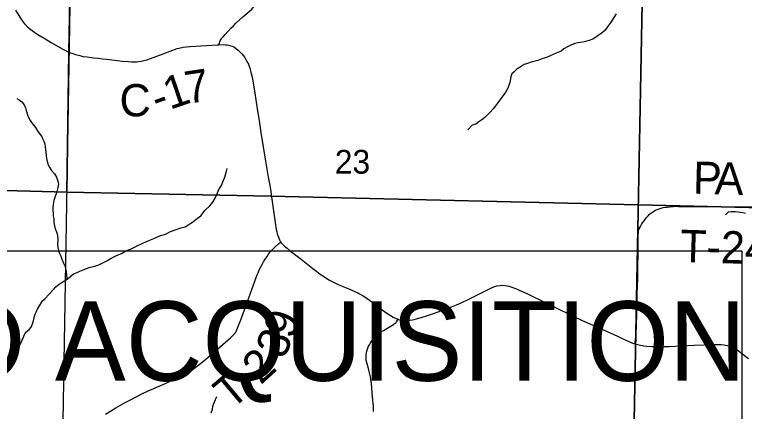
# Model space of a CAD drawing. Extents: x 0 to 34, y 0 to 22.
# Drawn here: x 11.356 to 12.641, y 17.147 to 17.845 of the extents above; entities that cross this region are included whole.
import ezdxf

# ---------------------------------------------------------------- set-up
doc = ezdxf.new("R2010")
doc.units = 0
for name, color, linetype in [('GM_X_Corporation', 7, 'Continuous'), ('GM_X_County_Road', 7, 'Continuous'), ('GM_X_County_Road_Text', 7, 'Continuous'), ('GM_X_Minor_River', 7, 'Continuous'), ('GM_X_Section_Text', 7, 'Continuous'), ('GM_X_Township_Road', 7, 'Continuous'), ('GM_X_Township_Road_Text', 7, 'Continuous'), ('SH_Text', 7, 'Continuous')]:
    doc.layers.add(name, color=color, linetype=linetype)

msp = doc.modelspace()

# ---------------------------------------------------------------- linework, layer by layer
at = {"layer": 'GM_X_Corporation'}
for points in [[(11.5001, 20.4), (10.6, 20.4), (10.6, 17.5523), (10.9447, 17.5459), (11.0329, 17.5442), (11.4477, 17.5329), (11.4514, 17.7789), (11.4741, 19.003), (11.486, 19.6423), (11.498, 20.2911)], [(10.6, 18.0532), (10.6, 17.0429), (11.4395, 17.0255), (11.4565, 18.0343)], [(11.4565, 18.0343), (12.4638, 18.0185), (12.4446, 17.0089), (11.4395, 17.0255)], [(12.4638, 18.0185), (13.4723, 18.0001), (13.4493, 16.9912), (12.4446, 17.0089)]]:
    msp.add_lwpolyline(points, close=True, dxfattribs=at)
for points in [[(16.7661, 20.4), (11.5001, 20.4), (11.498, 20.2911), (11.486, 19.6423), (11.4741, 19.003), (11.4514, 17.7789), (11.4477, 17.5329), (11.8073, 17.526), (12.504, 17.5091), (12.7693, 17.5027), (12.7967, 17.502), (13.2742, 17.4966), (14.0954, 17.4811)], [(14.0954, 17.4811), (13.2742, 17.4966), (12.7967, 17.502), (12.7693, 17.5027), (12.504, 17.5091), (11.8073, 17.526), (11.4477, 17.5329), (11.0329, 17.5442), (10.9447, 17.5459), (10.9437, 17.4908), (10.9418, 17.3896), (10.9206, 16.4568), (10.9139, 16.0819), (10.9086, 15.7107), (10.9052, 15.3502), (10.897, 14.5214)]]:
    msp.add_lwpolyline(points, dxfattribs=at)
at = {"layer": 'GM_X_County_Road'}
for points in [[(11.3577, 17.8529), (11.368, 17.8358), (11.3697, 17.8337), (11.3732, 17.8292), (11.3753, 17.827), (11.3794, 17.8232), (11.3842, 17.8192), (11.3914, 17.8139), (11.3967, 17.8103), (11.4079, 17.8037), (11.4205, 17.7963), (11.4354, 17.7875), (11.4405, 17.7846), (11.4489, 17.7804), (11.454, 17.7781), (11.4564, 17.7772)], [(11.4564, 17.7772), (11.4633, 17.775), (11.4707, 17.7731), (11.4763, 17.7718), (11.4836, 17.7707), (11.4948, 17.7693), (11.5031, 17.7684), (11.5107, 17.7676), (11.5175, 17.7667), (11.5271, 17.7657), (11.5369, 17.7646), (11.5453, 17.7635), (11.5567, 17.7625), (11.5616, 17.7622), (11.5672, 17.7621), (11.5709, 17.7622), (11.5745, 17.7626), (11.579, 17.7632), (11.5835, 17.7643), (11.5885, 17.7659), (11.5949, 17.768), (11.6173, 17.7761), (11.6423, 17.7854), (11.6478, 17.7869), (11.653, 17.7879), (11.6586, 17.7888), (11.6642, 17.7892), (11.6757, 17.7899), (11.6837, 17.7904), (11.6937, 17.7911), (11.7128, 17.7921), (11.7157, 17.7923), (11.7231, 17.7926), (11.727, 17.7923), (11.7296, 17.792), (11.7332, 17.7914), (11.7362, 17.7906), (11.7391, 17.7896), (11.7417, 17.7883), (11.7444, 17.7867), (11.7472, 17.7845), (11.7498, 17.7824), (11.753, 17.7793), (11.7559, 17.7763), (11.7586, 17.7731), (11.7613, 17.7695), (11.7633, 17.7664), (11.7651, 17.7629), (11.7676, 17.7578), (11.77, 17.751), (11.772, 17.7442), (11.7742, 17.7351), (11.7772, 17.7184), (11.779, 17.7069), (11.7831, 17.6793), (11.7859, 17.6624), (11.7897, 17.6378), (11.7979, 17.5872), (11.8026, 17.5591), (11.8051, 17.5444), (11.8063, 17.5374), (11.8089, 17.5208)], [(11.8089, 17.5208), (11.8168, 17.4671), (11.8176, 17.4632), (11.8184, 17.4597), (11.8193, 17.4566), (11.8216, 17.4508), (11.8226, 17.4488), (11.8237, 17.4468), (11.8247, 17.4452), (11.8256, 17.4439), (11.8272, 17.4419), (11.829, 17.44), (11.8312, 17.4379), (11.8356, 17.4341), (11.8419, 17.429), (11.8603, 17.4148), (11.8813, 17.3985), (11.888, 17.3933), (11.8942, 17.3887), (11.9034, 17.3825), (11.9094, 17.3788), (11.9129, 17.3767), (11.9219, 17.3721), (11.9256, 17.3703), (11.9346, 17.3666), (11.9398, 17.3646), (11.9461, 17.362), (11.9512, 17.3598), (11.9603, 17.3557), (11.9634, 17.3541), (11.97, 17.3504), (11.9729, 17.3486), (11.9809, 17.343), (11.987, 17.3387), (11.9951, 17.3325), (12.0033, 17.3257), (12.0113, 17.32), (12.0161, 17.3169), (12.0225, 17.313), (12.025, 17.3116), (12.0295, 17.3097), (12.0311, 17.3092), (12.0321, 17.3088), (12.0376, 17.3076), (12.04, 17.3072), (12.0423, 17.307), (12.0482, 17.3072), (12.0521, 17.3075), (12.0567, 17.3083), (12.0612, 17.3093), (12.0677, 17.3111), (12.0796, 17.3147), (12.0885, 17.3176), (12.1019, 17.3224), (12.1255, 17.3312), (12.1339, 17.3345), (12.1413, 17.3378), (12.158, 17.3458), (12.1664, 17.3501), (12.1908, 17.3624), (12.1969, 17.3652), (12.2019, 17.3668), (12.2053, 17.3678), (12.2109, 17.3687), (12.2131, 17.3689), (12.22, 17.3687), (12.2233, 17.3682), (12.2264, 17.3675), (12.2298, 17.3664), (12.2395, 17.3627), (12.2447, 17.3605), (12.2579, 17.3543), (12.2688, 17.3492), (12.3017, 17.3335), (12.3146, 17.3272), (12.3289, 17.3202), (12.3422, 17.3137), (12.3543, 17.3079), (12.3648, 17.3032), (12.41, 17.2829), (12.419, 17.2786), (12.4337, 17.2716), (12.4378, 17.2698), (12.4443, 17.2673), (12.4463, 17.2666), (12.448, 17.2661), (12.4533, 17.2648), (12.458, 17.2637), (12.4639, 17.2625), (12.4695, 17.262), (12.4779, 17.2614), (12.493, 17.2611), (12.5084, 17.2614), (12.5521, 17.2637), (12.5891, 17.265), (12.6005, 17.2647), (12.6058, 17.2641), (12.6079, 17.2637), (12.6113, 17.2629), (12.6149, 17.2618), (12.6175, 17.2608), (12.6241, 17.2579), (12.6267, 17.2564), (12.6302, 17.2541), (12.6339, 17.2515), (12.6486, 17.2402)]]:
    msp.add_lwpolyline(points, dxfattribs=at)
at = {"layer": 'GM_X_Minor_River'}
for points in [[(12.4155, 17.8467), (12.408, 17.8353), (12.405, 17.8304), (12.4012, 17.8254), (12.3959, 17.8178), (12.391, 17.8136), (12.3853, 17.8098), (12.3789, 17.8049), (12.3743, 17.8018), (12.3679, 17.7995), (12.3588, 17.7972), (12.3527, 17.7961), (12.3478, 17.7957), (12.3424, 17.7946), (12.3352, 17.7915), (12.3296, 17.7888), (12.3231, 17.785), (12.3182, 17.7812), (12.3099, 17.7774), (12.2992, 17.7729), (12.2924, 17.7698), (12.2864, 17.7679), (12.2773, 17.7645), (12.2727, 17.7633), (12.2655, 17.7618), (12.259, 17.7591)], [(12.259, 17.7591), (12.2534, 17.7572), (12.2462, 17.753), (12.2405, 17.7492), (12.2359, 17.7447), (12.2314, 17.7412), (12.2299, 17.7359), (12.228, 17.726), (12.2262, 17.7207), (12.2243, 17.7158), (12.2197, 17.7074), (12.2137, 17.7002), (12.2111, 17.6956), (12.2065, 17.6896), (12.2031, 17.6846), (12.1986, 17.6797), (12.1933, 17.6736), (12.1887, 17.669), (12.1842, 17.6641), (12.1789, 17.6603), (12.1736, 17.6568), (12.1679, 17.6527), (12.1615, 17.6508), (12.1539, 17.6428)], [(11.3595, 17.6977), (11.3641, 17.6954), (11.3686, 17.692), (11.3728, 17.6867), (11.3751, 17.681), (11.3763, 17.6764), (11.3786, 17.6688), (11.3805, 17.6643), (11.3832, 17.659), (11.3874, 17.6533), (11.3927, 17.6464), (11.3969, 17.6396), (11.403, 17.6316), (11.4049, 17.6271), (11.4072, 17.6225), (11.4091, 17.6176), (11.4099, 17.6123), (11.4111, 17.6035), (11.4115, 17.5975), (11.4119, 17.5918), (11.4142, 17.5819), (11.418, 17.5758), (11.4211, 17.5709), (11.426, 17.5648), (11.4295, 17.5591), (11.4321, 17.5519), (11.4329, 17.547), (11.4322, 17.5409), (11.4296, 17.5318), (11.4273, 17.5253), (11.4247, 17.5181), (11.4236, 17.5109), (11.4232, 17.506), (11.4232, 17.5006), (11.4236, 17.4953), (11.424, 17.4904), (11.4248, 17.4858), (11.4252, 17.4794), (11.4263, 17.4737), (11.4275, 17.4684), (11.4294, 17.4631), (11.4313, 17.4574), (11.4318, 17.4483), (11.4314, 17.4418), (11.4318, 17.4353), (11.433, 17.43), (11.4349, 17.4251), (11.4372, 17.4202), (11.4391, 17.4148), (11.4421, 17.408), (11.4444, 17.4031), (11.4456, 17.3985), (11.4467, 17.3928), (11.4475, 17.3879), (11.4481, 17.38)], [(11.6613, 17.4755), (11.6689, 17.48), (11.678, 17.4869), (11.6837, 17.491), (11.6871, 17.4956), (11.6912, 17.5013), (11.6999, 17.5089), (11.7052, 17.515), (11.709, 17.5222), (11.712, 17.529), (11.7154, 17.5378), (11.7207, 17.5458), (11.7226, 17.5511), (11.726, 17.5591), (11.7297, 17.572), (11.7305, 17.5745)], [(12.6434, 17.4951), (12.6385, 17.4962), (12.6301, 17.4977), (12.6248, 17.4981), (12.6187, 17.4981), (12.6127, 17.4977), (12.6081, 17.4931)], [(11.3554, 17.2507), (11.3595, 17.256), (11.3652, 17.2636), (11.3682, 17.2693), (11.372, 17.2792), (11.375, 17.2857), (11.3814, 17.291), (11.3848, 17.2955), (11.3875, 17.3009), (11.389, 17.3066), (11.3901, 17.3115), (11.3916, 17.3168), (11.3938, 17.3218), (11.3961, 17.3271), (11.3999, 17.3328), (11.4048, 17.3415), (11.4097, 17.3457), (11.4161, 17.3525), (11.4245, 17.3617), (11.4282, 17.3662), (11.4343, 17.3712), (11.4396, 17.3746), (11.4464, 17.3788), (11.4547, 17.3852), (11.4597, 17.389), (11.4661, 17.3917), (11.471, 17.3936), (11.4767, 17.3959), (11.487, 17.4001), (11.4991, 17.4031), (11.504, 17.405), (11.5184, 17.4123), (11.5271, 17.4172), (11.5332, 17.4203), (11.5393, 17.4229), (11.5442, 17.4252), (11.5518, 17.4298), (11.5601, 17.4324), (11.5719, 17.4385), (11.5817, 17.4431), (11.5923, 17.448), (11.6011, 17.4515), (11.6128, 17.4564), (11.6196, 17.4583), (11.6242, 17.4602), (11.6306, 17.4636), (11.6424, 17.4678), (11.6484, 17.4701), (11.6564, 17.4717), (11.6613, 17.4755)], [(11.7023, 17.1448), (11.7042, 17.1512), (11.705, 17.1558), (11.7068, 17.1607), (11.7095, 17.1679), (11.7123, 17.1733)]]:
    msp.add_lwpolyline(points, dxfattribs=at)
at = {"layer": 'GM_X_Township_Road'}
for points in [[(11.7157, 17.7923), (11.7167, 17.7956), (11.718, 17.7993), (11.7194, 17.8018), (11.7206, 17.8036), (11.7229, 17.8063), (11.7265, 17.8105), (11.7369, 17.8213), (11.7413, 17.8257), (11.7457, 17.8302), (11.7515, 17.8355), (11.7577, 17.8411), (11.765, 17.8474), (11.7735, 17.8551), (11.7756, 17.857), (11.7782, 17.8601), (11.7816, 17.8646)], [(12.448, 17.2661), (12.4485, 17.2679), (12.4496, 17.2745), (12.4498, 17.277), (12.4507, 17.2889), (12.4509, 17.2944), (12.4525, 17.3542), (12.4529, 17.3682), (12.4532, 17.3801), (12.4537, 17.4055), (12.454, 17.4213), (12.4541, 17.4475), (12.4543, 17.4575), (12.4546, 17.4613), (12.4548, 17.464), (12.4554, 17.4665), (12.4564, 17.4692), (12.4579, 17.4725), (12.46, 17.4757), (12.4619, 17.4788), (12.4663, 17.4849), (12.4688, 17.4883), (12.4714, 17.4914), (12.4734, 17.4933), (12.4765, 17.4958), (12.4794, 17.4979), (12.4819, 17.4994), (12.4847, 17.5009), (12.4878, 17.5023), (12.491, 17.5036), (12.4945, 17.5047), (12.498, 17.5056), (12.5007, 17.5062), (12.505, 17.5067), (12.5096, 17.5072), (12.5134, 17.5076), (12.5158, 17.5077), (12.5189, 17.508)], [(12.5189, 17.508), (12.525, 17.5079), (12.5351, 17.5079), (12.5535, 17.5075), (12.5747, 17.5073), (12.6286, 17.5074), (12.6403, 17.5073), (12.6478, 17.5072), (12.6763, 17.5069), (12.6865, 17.5062)], [(11.5158, 17.1423), (11.5343, 17.1533), (11.5505, 17.1625), (11.5609, 17.1682), (11.5688, 17.1724), (11.5789, 17.1774), (11.5909, 17.1831), (11.6008, 17.1875), (11.6242, 17.1973), (11.63, 17.2), (11.6384, 17.2038), (11.6462, 17.2076), (11.6526, 17.2108), (11.655, 17.2121), (11.6632, 17.2169), (11.6671, 17.2195), (11.671, 17.2221), (11.6758, 17.2255), (11.6806, 17.2292), (11.6929, 17.2391), (11.7007, 17.2458), (11.7362, 17.2768), (11.7377, 17.2782), (11.7409, 17.281), (11.7435, 17.284), (11.7452, 17.2865), (11.7466, 17.289), (11.7491, 17.2953), (11.7541, 17.3083), (11.7582, 17.3191), (11.7814, 17.3828), (11.7832, 17.3873), (11.7848, 17.3911), (11.7874, 17.3971), (11.7894, 17.4012), (11.7916, 17.4053), (11.7945, 17.4105), (11.7974, 17.4152), (11.8004, 17.4199), (11.8038, 17.4248), (11.8066, 17.4283), (11.811, 17.4331), (11.8139, 17.4359), (11.8214, 17.4425), (11.823, 17.4438), (11.8247, 17.4452)], [(11.988, 17.1467), (11.988, 17.1495), (11.9881, 17.1521), (11.9879, 17.1562), (11.9875, 17.1617), (11.987, 17.1674), (11.9858, 17.1795), (11.9851, 17.1885), (11.9842, 17.1964), (11.9834, 17.2024), (11.9824, 17.2078), (11.9808, 17.2152), (11.9795, 17.2204), (11.9757, 17.2346), (11.9753, 17.2367), (11.975, 17.2399), (11.9749, 17.2436), (11.975, 17.2465), (11.9756, 17.2512), (11.9761, 17.2532), (11.9772, 17.2566), (11.9787, 17.2605), (11.9807, 17.2642), (11.9827, 17.2676), (11.9854, 17.2716), (11.9882, 17.2753), (11.9907, 17.2779), (11.9938, 17.281), (11.9972, 17.2837), (12.0016, 17.2868), (12.0057, 17.2894), (12.0231, 17.2998), (12.0246, 17.3009), (12.0263, 17.3021), (12.0278, 17.3037), (12.0285, 17.3047), (12.0305, 17.3079), (12.0311, 17.3092)]]:
    msp.add_lwpolyline(points, dxfattribs=at)
at = {"layer": 'SH_Text'}
msp.add_lwpolyline([(10.9396, 17.4298), (12.6369, 17.4298), (12.6369, 16.7049), (10.9396, 16.7049)], close=True, dxfattribs=at)

# ---------------------------------------------------------------- texts
at = {"layer": 'GM_X_County_Road_Text'}
for s, rotation, p in [('1', 18.8315, (11.6292, 17.6775)), ('7', 8.5665, (11.6598, 17.6882)), ('C', 0.7884, (11.5411, 17.6658)), ('-', 19.1646, (11.6073, 17.6699))]:
    msp.add_text(s, height=0.0568, rotation=rotation, dxfattribs=at).set_placement(p)
at = {"layer": 'GM_X_Section_Text'}
msp.add_text('23', height=0.04186, rotation=0, dxfattribs=at).set_placement((11.9198, 17.5654))
at = {"layer": 'GM_X_Township_Road_Text'}
for s, height, rotation, p in [('P', 0.0568, 358.4556, (12.55, 17.5302)), ('A', 0.0568, 358.4593, (12.5883, 17.5292)), ('T-248', 0.05682, 358.3152, (12.5273, 17.4101)), ('9', 0.0568, 69.6112, (11.8455, 17.2725)), ('3', 0.0568, 66.3681, (11.8301, 17.2372)), ('2', 0.0568, 42.3568, (11.7892, 17.1927)), ('T', 0.0568, 40.1639, (11.7372, 17.1485)), ('-', 0.0568, 40.4833, (11.77, 17.1762))]:
    msp.add_text(s, height=height, rotation=rotation, dxfattribs=at).set_placement(p)
at = {"layer": 'SH_Text'}
msp.add_text('END ACQUISITION', height=0.14, dxfattribs=at).set_placement((10.9795, 17.2009))

doc.saveas('drawing.dxf')
